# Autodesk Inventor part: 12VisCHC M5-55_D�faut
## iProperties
Created: 2011-01
Part Number: 12VisCHC M5-55_D�faut
Document SubType Name: Modeling
Designer: eric
Density: 1 g/cm^3
Mass: 1.32578 g
Surface Area: 11.3482 cm^2
Volume: 1.32578 cm^3
Author: eric
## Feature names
1. Base1
